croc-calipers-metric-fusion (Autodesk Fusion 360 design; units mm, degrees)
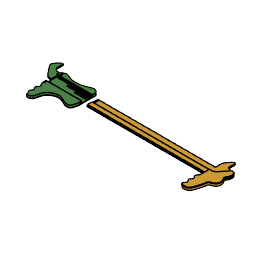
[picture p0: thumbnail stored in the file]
named bodies: "rule_main_body", "eye1_wt", "eye2_wt", "eye1center_blk", "eye2center_blk", "freckle1_blk", "freckle2_blk", "freckle3_blk", "freckle4_blk", "freckle5_blk", "eyebrow1_blk", "freckle6_blk", "eyebrow2_blk", "slide_body", "slide_ticmark_btm", "slide_ticmark_top", "scale_top_blk", "scale_btm_blk", "text (44)", "text (38)", "text (16)", "text (40)", "text (43)", "text (37)", "text (45)", "text (39)", "text (42)", "text (20)", "text (36)", "text (35)", "text (33)", "text (26)", "text (32)", "text (18)", "text (31)", "text (34)", "text (30)", "text (29)", "text (24)", "text (21)", "text (23)", "text (13)", "text (17)", "text (27)", "text (25)", "text (15)", "text (28)", "text (22)", "text (14)", "text (51)", "text (49)", "text (48)", "text (47)", "text (46)", "text (54)", "text (52)", "text (53)", "text (50)", "text (12)", "text (11)"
